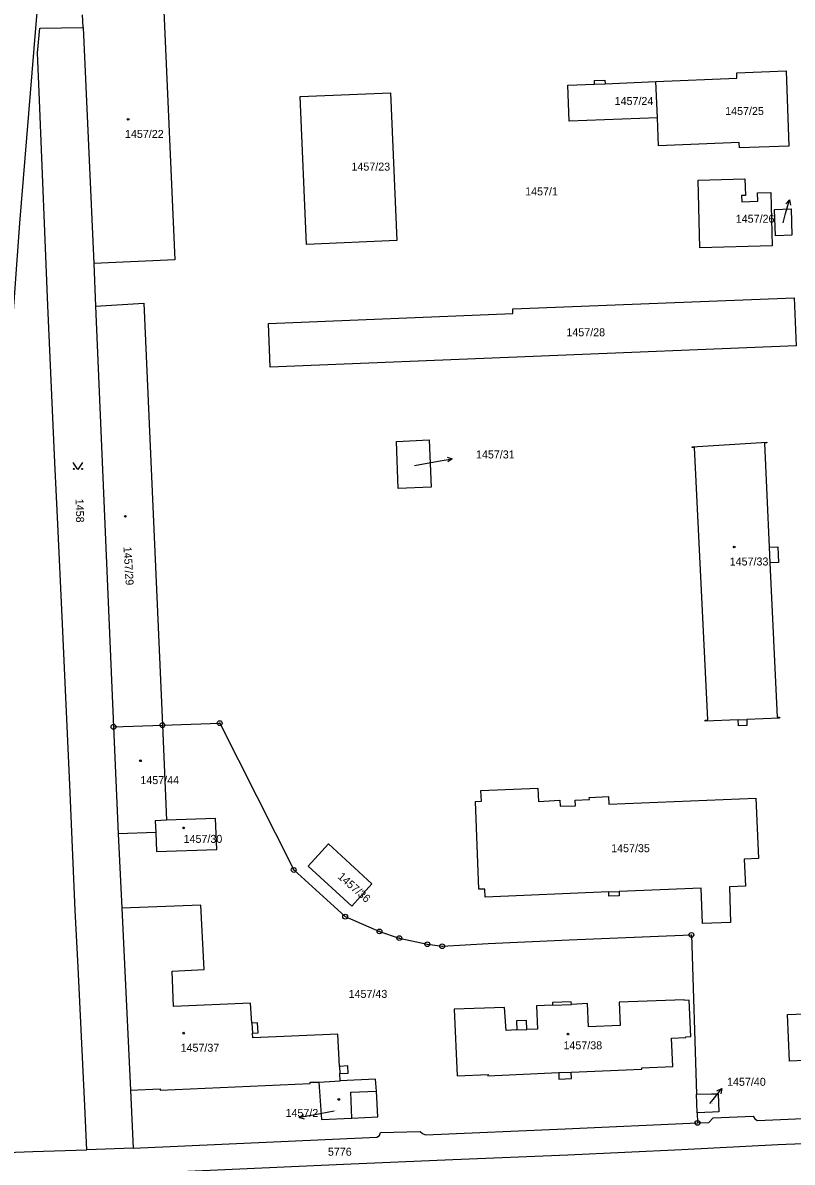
# Model space of a CAD drawing. Extents: x -736397 to -735924, y -1118983 to -1118245.
# Drawn here: x -736247 to -736083.5, y -1118835.5 to -1118593.4 of the extents above; entities that cross this region are included whole.
import ezdxf

# ---------------------------------------------------------------- set-up
doc = ezdxf.new("R2010")
doc.units = 0
for name, color, linetype in [('Vrstva 1', 7, 'Continuous'), ('Vrstva 16', 7, 'Continuous'), ('Vrstva 18', 7, 'Continuous'), ('Vrstva 19', 7, 'Continuous'), ('Vrstva 25', 7, 'Continuous'), ('Vrstva 4', 7, 'Continuous')]:
    doc.layers.add(name, color=color, linetype=linetype)

msp = doc.modelspace()

# ---------------------------------------------------------------- linework, layer by layer
at = {"layer": 'Vrstva 1'}
for p, q in [((-736234.13, -1118594.46), (-736234.25, -1118591.7)), ((-736234.13, -1118594.46), (-736231.89, -1118644.57)), ((-736123.21, -1118606.36), (-736112.44, -1118605.92)), ((-736112.1, -1118613.59), (-736112.44, -1118605.92)), ((-736231.89, -1118644.57), (-736231.53, -1118653.6)), ((-736231.53, -1118653.6), (-736227.69, -1118743)), ((-736227.69, -1118743), (-736217.28, -1118742.64)), ((-736217.28, -1118742.64), (-736216.38, -1118762.85)), ((-736227.69, -1118743), (-736226.71, -1118765.69)), ((-736218.71, -1118765.41), (-736226.71, -1118765.69)), ((-736226.71, -1118765.69), (-736225.91, -1118781.54)), ((-736225.91, -1118781.54), (-736224.09, -1118820.19)), ((-736179.49, -1118818.22), (-736179.58, -1118816.64)), ((-736224.09, -1118820.19), (-736223.48, -1118832.5)), ((-736184.03, -1118818.45), (-736179.49, -1118818.22)), ((-736103.64, -1118824.99), (-736103.77, -1118821.04)), ((-736103.64, -1118824.99), (-736103.57, -1118827.14)), ((-736223.48, -1118832.5), (-736233.37, -1118832.85))]:
    msp.add_line(p, q, dxfattribs=at)
for points in [[(-736227.49, -1118462.99), (-736228.6, -1118463.11), (-736230.07, -1118469.05), (-736237.36, -1118522.21), (-736239.9, -1118543.95), (-736244.25, -1118594.56), (-736247.64, -1118635.96), (-736251.91, -1118694.01)], [(-736217, -1118590.94), (-736214.63, -1118643.77), (-736231.89, -1118644.57)], [(-736233.37, -1118832.85), (-736233.85, -1118822.03), (-736235.15, -1118794.05), (-736235.82, -1118781.97), (-736236.94, -1118755.31), (-736238.59, -1118719.65), (-736239.51, -1118699.94), (-736240.11, -1118686.86), (-736241.66, -1118653.45), (-736243.37, -1118609.84), (-736243.86, -1118599.81), (-736243.31, -1118594.57), (-736234.13, -1118594.46)], [(-736112.44, -1118605.92), (-736095.24, -1118605.22), (-736095.22, -1118604.07), (-736084.74, -1118603.66), (-736084.19, -1118619.62), (-736094.67, -1118620.02), (-736094.72, -1118618.86), (-736111.87, -1118619.54), (-736112.1, -1118613.59)], [(-736112.1, -1118613.59), (-736130.86, -1118614.33), (-736131.16, -1118606.69), (-736125.49, -1118606.46)], [(-736125.49, -1118606.46), (-736125.5, -1118605.72), (-736123.28, -1118605.63), (-736123.21, -1118606.36)], [(-736188.02, -1118609.1), (-736168.81, -1118608.27), (-736167.47, -1118639.69), (-736186.7, -1118640.51), (-736188.02, -1118609.1)], [(-736093.41, -1118630.09), (-736094.21, -1118630.11), (-736094.18, -1118631.44), (-736090.79, -1118631.35), (-736090.83, -1118629.54), (-736088.02, -1118629.46), (-736087.72, -1118640.78), (-736103.07, -1118641.2), (-736103.46, -1118626.85), (-736093.51, -1118626.58), (-736093.41, -1118630.09)], [(-736086.99, -1118638.69), (-736087.2, -1118633.1), (-736083.7, -1118632.97), (-736083.51, -1118638.57), (-736086.99, -1118638.69)], [(-736231.53, -1118653.6), (-736221.25, -1118653.01), (-736217.28, -1118742.64)], [(-736194.72, -1118657.34), (-736142.81, -1118655.17), (-736142.84, -1118654.21), (-736083.01, -1118651.84), (-736082.64, -1118662.07), (-736194.4, -1118666.58), (-736194.72, -1118657.34)], [(-736167.18, -1118692.39), (-736167.54, -1118682.36), (-736160.63, -1118682.05), (-736160.19, -1118692.09), (-736167.18, -1118692.39)], [(-736094.96, -1118741.48), (-736101.97, -1118741.76), (-736101.98, -1118741.56), (-736101.42, -1118741.54), (-736104.19, -1118683.65), (-736104.74, -1118683.68), (-736104.75, -1118683.48), (-736088.83, -1118682.49), (-736088.82, -1118682.69), (-736089.37, -1118682.72), (-736088.35, -1118704.85)], [(-736088.35, -1118704.85), (-736086.55, -1118704.76), (-736086.38, -1118708.1), (-736088.2, -1118708.18)], [(-736088.2, -1118708.18), (-736086.69, -1118740.94), (-736086.14, -1118740.92), (-736086.13, -1118741.12), (-736093.13, -1118741.4)], [(-736217.28, -1118742.64), (-736205.1, -1118742.21), (-736189.38, -1118773.4), (-736178.44, -1118783.32), (-736171.15, -1118786.46), (-736166.95, -1118787.88), (-736160.99, -1118789.18), (-736157.84, -1118789.6), (-736148.09, -1118789.02), (-736130.83, -1118788.24), (-736110.16, -1118787.42), (-736104.88, -1118787.2), (-736103.77, -1118821.04)], [(-736093.13, -1118741.4), (-736093.08, -1118742.72), (-736094.9, -1118742.79), (-736094.96, -1118741.48)], [(-736122.45, -1118778.08), (-736148.69, -1118779.19), (-736148.76, -1118777.49), (-736150.05, -1118777.45), (-736150.78, -1118758.88), (-736149.51, -1118758.81), (-736149.6, -1118756.55), (-736137.52, -1118756.05), (-736137.4, -1118758.86), (-736132.81, -1118758.58), (-736132.76, -1118759.87), (-736129.54, -1118759.74), (-736129.59, -1118758.54), (-736126.56, -1118758.45), (-736126.58, -1118758.01), (-736122.47, -1118757.81), (-736122.4, -1118759.45), (-736091.17, -1118758.18), (-736090.64, -1118770.97), (-736093.68, -1118771.08), (-736093.4, -1118776.85), (-736096.8, -1118776.99), (-736096.56, -1118784.54), (-736102.55, -1118784.74), (-736102.84, -1118777.25), (-736120.24, -1118777.99)], [(-736216.38, -1118762.85), (-736218.81, -1118762.94), (-736218.71, -1118765.41)], [(-736218.71, -1118765.41), (-736218.56, -1118769.5), (-736205.75, -1118769.02), (-736206.02, -1118762.46), (-736216.38, -1118762.85)], [(-736186.33, -1118772.58), (-736182.01, -1118767.87), (-736172.77, -1118776.38), (-736177.03, -1118781.09), (-736186.33, -1118772.58)], [(-736048.25, -1118773.91), (-736041.17, -1118773.63), (-736039.64, -1118812.27), (-736046.04, -1118812.52), (-736046.03, -1118812.82), (-736077.68, -1118814.07), (-736077.69, -1118813.77), (-736084.04, -1118814.04), (-736084.45, -1118804.09), (-736066.24, -1118803.37), (-736066.52, -1118795.92), (-736050.18, -1118795.36), (-736050.48, -1118787.78), (-736057.23, -1118787.99), (-736057.82, -1118774.29), (-736050.37, -1118773.99)], [(-736120.24, -1118777.99), (-736120.2, -1118778.88), (-736122.42, -1118778.98), (-736122.45, -1118778.08)], [(-736198.3, -1118805.98), (-736198.58, -1118801.71), (-736214.9, -1118802.43), (-736215.23, -1118794.87), (-736208.41, -1118794.57), (-736209.13, -1118780.89), (-736225.91, -1118781.54)], [(-736141.97, -1118807.39), (-736144.27, -1118807.49), (-736144.56, -1118802.62), (-736155.28, -1118803), (-736154.63, -1118817.1), (-736148.08, -1118816.83), (-736148.11, -1118817.12), (-736133.08, -1118816.46)], [(-736134.36, -1118802.12), (-736137.8, -1118802.27), (-736137.55, -1118807.2), (-736139.85, -1118807.3)], [(-736130.39, -1118801.95), (-736130.43, -1118801.38), (-736134.4, -1118801.53), (-736134.36, -1118802.12)], [(-736130.43, -1118816.35), (-736115.43, -1118815.69), (-736115.41, -1118815.42), (-736108.82, -1118815.13), (-736109.08, -1118809.11), (-736106.07, -1118808.99), (-736106.08, -1118808.84), (-736105.02, -1118808.81), (-736105.33, -1118801.04), (-736106.38, -1118801.1), (-736106.39, -1118800.96), (-736120.24, -1118801.5), (-736120.03, -1118806.42), (-736126.75, -1118806.71), (-736126.97, -1118801.8), (-736130.39, -1118801.95)], [(-736139.85, -1118807.3), (-736139.92, -1118805.41), (-736142.06, -1118805.45), (-736141.97, -1118807.39)], [(-736198.17, -1118808.05), (-736196.92, -1118807.97), (-736197.07, -1118805.9), (-736198.3, -1118805.98)], [(-736179.66, -1118815.14), (-736180.04, -1118808.25), (-736198.1, -1118809.07), (-736198.17, -1118808.05)], [(-736179.58, -1118816.64), (-736177.83, -1118816.55), (-736177.9, -1118815.04), (-736179.66, -1118815.14)], [(-736171.82, -1118820.36), (-736171.98, -1118817.82), (-736179.49, -1118818.22)], [(-736133.08, -1118816.46), (-736133.02, -1118817.83), (-736130.37, -1118817.71), (-736130.43, -1118816.35)], [(-736224.09, -1118820.19), (-736217.75, -1118819.9), (-736217.74, -1118820.2), (-736185.91, -1118818.78), (-736185.92, -1118818.48), (-736184.03, -1118818.45)], [(-736184.03, -1118818.45), (-736183.51, -1118826.42), (-736177.01, -1118826.1)], [(-736177.01, -1118826.1), (-736171.49, -1118825.83), (-736171.82, -1118820.36)], [(-736103.77, -1118821.04), (-736100.59, -1118820.98), (-736099.17, -1118820.96), (-736099.03, -1118824.79), (-736100.4, -1118824.84), (-736103.64, -1118824.99)], [(-736103.57, -1118827.14), (-736101.2, -1118827.04), (-736100.24, -1118826.04), (-736091.75, -1118825.67), (-736091.43, -1118826.29), (-736090.86, -1118826.61), (-736029.2, -1118823.96), (-736025.68, -1118823.89)], [(-736223.48, -1118832.5), (-736171.73, -1118830.16), (-736171.13, -1118829.84), (-736170.92, -1118829.15), (-736162.49, -1118828.94), (-736162.04, -1118829.42), (-736161.38, -1118829.7), (-736131.72, -1118828.39), (-736103.57, -1118827.14)], [(-735928.04, -1118863.01), (-735953.25, -1118853.19), (-735997.4, -1118835.89), (-736016.73, -1118829.28), (-736030.6, -1118829.59), (-736086.48, -1118831.76), (-736106.94, -1118832.82), (-736131.16, -1118833.96), (-736155.56, -1118834.99), (-736178.79, -1118836), (-736244.96, -1118838.93), (-736275.1, -1118839.95)], [(-736270.78, -1118834.19), (-736244.82, -1118833.2), (-736233.37, -1118832.85)]]:
    msp.add_lwpolyline(points, dxfattribs=at)
at = {"layer": 'Vrstva 16'}
for points in [[(-736085.41, -1118635.89), (-736084.86, -1118633.96), (-736084.04, -1118631.07)], [(-736084.79, -1118631.9), (-736084.04, -1118631.07), (-736083.83, -1118632.17)], [(-736163.71, -1118687.48), (-736158.68, -1118686.58), (-736155.73, -1118686.05)], [(-736156.8, -1118685.73), (-736155.73, -1118686.05), (-736156.62, -1118686.72)], [(-736100.95, -1118823.03), (-736100.29, -1118822.19), (-736098.44, -1118819.83)], [(-736099.45, -1118820.31), (-736098.44, -1118819.83), (-736098.66, -1118820.93)], [(-736180.79, -1118824.62), (-736185.25, -1118825.46), (-736188.2, -1118826.01)], [(-736187.12, -1118826.32), (-736188.2, -1118826.01), (-736187.31, -1118825.34)]]:
    msp.add_lwpolyline(points, dxfattribs=at)
at = {"layer": 'Vrstva 25'}
msp.add_lwpolyline([(-736234.23, -1118686.81), (-736235.23, -1118688.31), (-736236.23, -1118686.81)], dxfattribs=at)
for centre in [(-736236.13, -1118688.21), (-736234.33, -1118688.21)]:
    msp.add_circle(centre, 0.1, dxfattribs=at)
for centre, major_axis in [((-736224.57, -1118613.92), (0.18, 0)), ((-736225.16, -1118698.27), (0.18, 0)), ((-736095.79, -1118704.78), (0.18, 0)), ((-736227.69, -1118743), (0.516, 0)), ((-736217.28, -1118742.64), (0.516, 0)), ((-736217.28, -1118742.64), (0.0375, 0)), ((-736205.1, -1118742.21), (0.516, 0)), ((-736205.1, -1118742.21), (0.0375, 0)), ((-736227.69, -1118743), (0.0375, 0)), ((-736221.95, -1118750.2), (0.18, 0)), ((-736212.76, -1118764.45), (0.18, 0)), ((-736189.38, -1118773.4), (0.516, 0)), ((-736189.38, -1118773.4), (0.0375, 0)), ((-736178.44, -1118783.32), (0.516, 0)), ((-736178.44, -1118783.32), (0.0375, 0)), ((-736171.15, -1118786.46), (0.516, 0)), ((-736171.15, -1118786.46), (0.0375, 0)), ((-736166.95, -1118787.88), (0.516, 0)), ((-736166.95, -1118787.88), (0.0375, 0)), ((-736160.99, -1118789.18), (0.516, 0)), ((-736104.88, -1118787.2), (0.516, 0)), ((-736104.88, -1118787.2), (0.0375, 0)), ((-736160.99, -1118789.18), (0.0375, 0)), ((-736157.84, -1118789.6), (0.516, 0)), ((-736157.84, -1118789.6), (0.0375, 0)), ((-736212.76, -1118808.07), (0.18, 0)), ((-736131.1, -1118808.27), (0.18, 0)), ((-736179.8, -1118822.15), (0.18, 0)), ((-736103.57, -1118827.14), (0.516, 0)), ((-736103.57, -1118827.14), (0.0375, 0))]:
    msp.add_ellipse(centre, major_axis=major_axis, ratio=0.984808, dxfattribs=at)
at = {"layer": 'Vrstva 4'}
for p, q in [((-736125.49, -1118606.46), (-736123.21, -1118606.36)), ((-736088.35, -1118704.85), (-736088.2, -1118708.18)), ((-736094.96, -1118741.48), (-736093.13, -1118741.4)), ((-736122.45, -1118778.08), (-736120.24, -1118777.99)), ((-736134.36, -1118802.12), (-736130.39, -1118801.95)), ((-736198.3, -1118805.98), (-736198.17, -1118808.05)), ((-736141.97, -1118807.39), (-736139.85, -1118807.3)), ((-736179.66, -1118815.14), (-736179.58, -1118816.64)), ((-736133.08, -1118816.46), (-736130.43, -1118816.35))]:
    msp.add_line(p, q, dxfattribs=at)
msp.add_lwpolyline([(-736177.01, -1118826.1), (-736177.28, -1118820.63), (-736171.82, -1118820.36)], dxfattribs=at)

# ---------------------------------------------------------------- texts
at = {"layer": 'Vrstva 16'}
for s, p in [('1457/31', (-736150.65, -1118685.98)), ('1457/40', (-736097.3, -1118819.25)), ('1457/2', (-736191.12, -1118825.87))]:
    msp.add_text(s, height=1.7, dxfattribs=at).set_placement(p)
at = {"layer": 'Vrstva 18'}
for s, height, p in [('1457/24', 1.7, (-736121.19, -1118610.89)), ('1457/25', 1.7, (-736097.7, -1118613.02)), ('1457/23', 1.7, (-736177.11, -1118624.83)), ('1457/1', 1.7, (-736140.2, -1118630.09)), ('1457/26', 1.7, (-736095.45, -1118635.9)), ('1457/41', 0.1, (-736085.41, -1118635.89)), ('1457/28', 1.7, (-736131.44, -1118660.02)), ('1457/31', 0.1, (-736163.71, -1118687.48)), ('1457/35', 1.7, (-736121.93, -1118769.63)), ('1457/43', 1.7, (-736177.72, -1118800.58)), ('1457/40', 0.1, (-736100.95, -1118823.03)), ('5776', 1.7, (-736182.12, -1118834.11))]:
    msp.add_text(s, height=height, dxfattribs=at).set_placement(p)
for s, rotation, p in [('1458', 271.6406, (-736235.75, -1118694.57)), ('1457/36', 318.4845, (-736180.16, -1118775.02))]:
    msp.add_text(s, height=1.7, rotation=rotation, dxfattribs=at).set_placement(p)
at = {"layer": 'Vrstva 19'}
for s, height, p in [('1457/22', 1.7, (-736225.23, -1118617.89)), ('1457/33', 1.7, (-736096.74, -1118708.72)), ('1457/44', 1.7, (-736221.96, -1118755.16)), ('1457/30', 1.7, (-736212.78, -1118767.65)), ('1457/37', 1.7, (-736213.42, -1118812.02)), ('1457/38', 1.7, (-736132.06, -1118811.5)), ('1457/2', 0.1, (-736180.61, -1118824.62))]:
    msp.add_text(s, height=height, dxfattribs=at).set_placement(p)
msp.add_text('1457/29', height=1.7, rotation=273.5284, dxfattribs=at).set_placement((-736225.57, -1118704.77))

doc.saveas('drawing.dxf')
